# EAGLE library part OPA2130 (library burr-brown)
Operational Amplifier
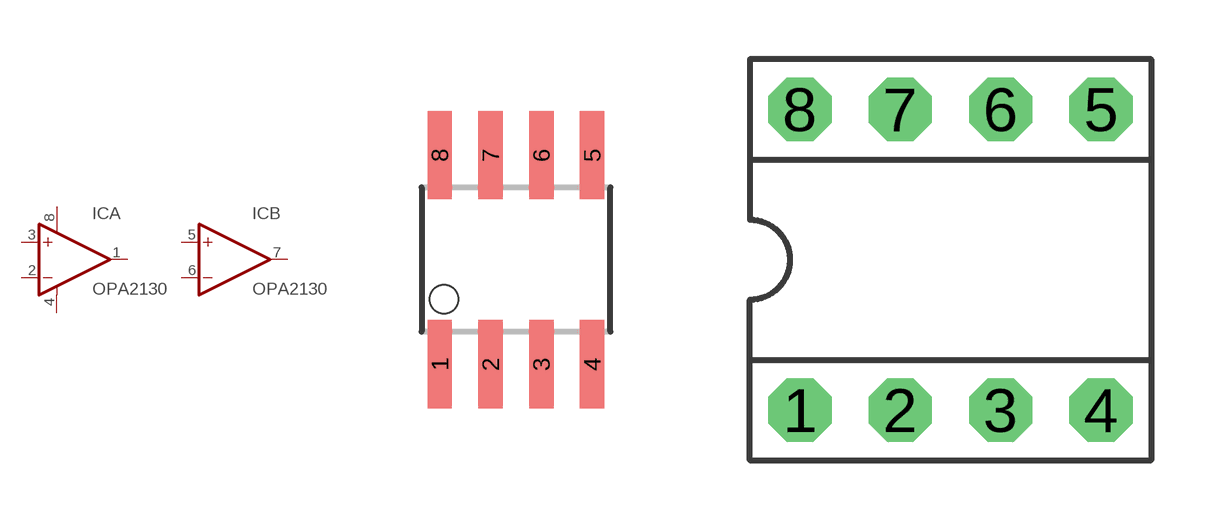
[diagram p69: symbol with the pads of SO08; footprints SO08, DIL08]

Designator prefix IC; gates B=OP-AMP A=OP-AMP+-

## OPA2130U (MF: TEXAS INSTRUMENTS; MPN: OPA2130UA; OC_FARNELL: 1459554; OC_NEWARK: 35C1841)  [SO08]
1  A:OUT  out
2  A:-IN  in
3  A:+IN  in
4  A:V-  pwr
5  B:+IN  in
6  B:-IN  in
7  B:OUT  out
8  A:V+  pwr

## OPA2130P (OC_FARNELL: unknown; OC_NEWARK: unknown)  [DIL08]
Pads as for SO08

## Footprint SO08 (pad centres in mm)
Small Outline Package
smd 0.61 x 2.21: 1 -1.905,-2.616; 2 -0.635,-2.616; 3 0.635,-2.616; 4 1.905,-2.616; 5 1.905,2.616; 6 0.635,2.616; 7 -0.635,2.616; 8 -1.905,2.616

## Footprint DIL08 (pad centres in mm)
Dual In Line
drill 0.813 pad 1.6 octagon: 1 -3.81,-3.81; 2 -1.27,-3.81; 3 1.27,-3.81; 4 3.81,-3.81; 5 3.81,3.81; 6 1.27,3.81; 7 -1.27,3.81; 8 -3.81,3.81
